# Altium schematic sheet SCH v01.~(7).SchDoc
size A3; SheetNumber: 1; SheetTotal: 1
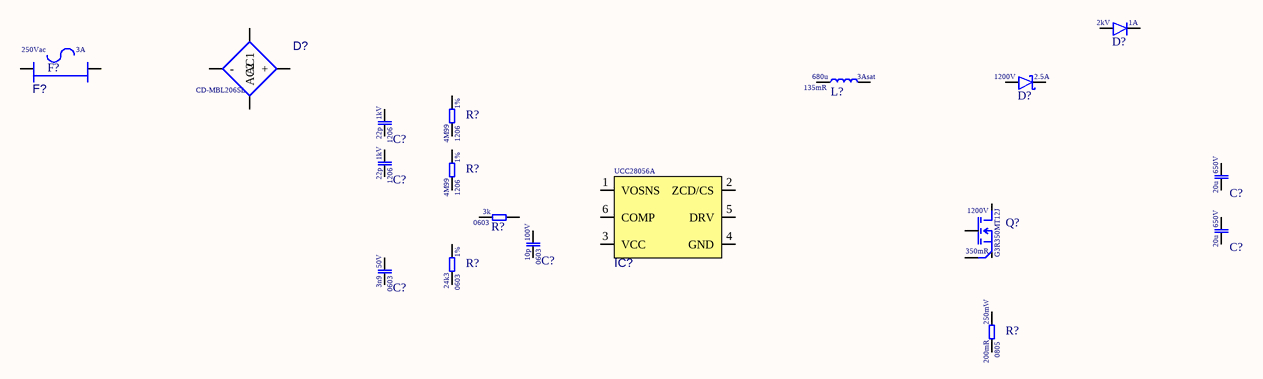
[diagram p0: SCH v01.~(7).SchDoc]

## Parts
(Parts that share a designator on the sheet are numbered #1, #2 ... from top to bottom, then left to right.)
C?#1  Voltage Rating: 1kV  Case Code (Imperial): 1206  Capacitance: 22p  [Cap_1206]  (hidden comment: Generic Capacitor model)
C?#2  Voltage Rating: 1kV  Case Code (Imperial): 1206  Capacitance: 22p  [Cap_1206]  (hidden comment: Generic Capacitor model)
C?#3  Voltage Rating: 650V  Capacitance: 20u  [C4AQCBW5200A3FJ]  (hidden comment: Generic Capacitor model)
C?#4  Voltage Rating: 650V  Capacitance: 20u  [C4AQCBW5200A3FJ]  (hidden comment: Generic Capacitor model)
C?#5  Voltage Rating: 100V  Case Code (Imperial): 0603  Capacitance: 10p  [CAP 0603]  (hidden comment: Generic Capacitor model)
C?#6  Voltage Rating: 50V  Case Code (Imperial): 0603  Capacitance: 3n9  [CAP 0603]  (hidden comment: Generic Capacitor model)
D?#1  Forward Current: 1A  Reverse Voltage: 2kV  [SOD-123FL]  (hidden comment: Diode)
D?#2  CD-MBL206SL  [CD-MBL206SL]
D?#3  Forward Current: 2.5A  Reverse Voltage: 1200V  [DO-214-2]  (hidden comment: Diode Schottky)
F?#1  Voltage: 250Vac  Hold Current: 3A  (hidden comment: Fuse no FP)  (graphical)
F?#2  64600001003  [64600001003]  (value not drawn)
IC?  UCC28056A  [SOT-23-6]
L?  Resistance: 135mR  Saturation current: 3Asat  Inductance: 680u  [60B684C]  (hidden comment: Inductor)
Q?  Manufacturer Part Number: G3R350MT12J  Rds: 350mR  Voltage: 1200V  [TO-263-7 D2PAK]  (hidden comment: Nmos_KS)
R?#1  Resistance Tolerance: 1%  Resistance: 4M99  Case Code (Imperial): 1206  [RES_1206]  (hidden comment: Generic resistor model)
R?#2  Resistance Tolerance: 1%  Resistance: 4M99  Case Code (Imperial): 1206  [RES_1206]  (hidden comment: Generic resistor model)
R?#3  Resistance: 3k  Case Code (Imperial): 0603  [RES_0603]  (hidden comment: Generic resistor model)
R?#4  Resistance Tolerance: 1%  Resistance: 24k3  Case Code (Imperial): 0603  [RES_0603]  (hidden comment: Generic resistor model)
R?#5  Resistance: 200mR  Power Rating: 250mW  Case Code (Imperial): 0805  [Res_0805]  (hidden comment: Generic resistor model)

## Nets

Not connected (* = marked no-connect by the designer): C?#1 1 2; C?#2 1 2; C?#3 1 2; C?#4 1 2; C?#5 1 2; C?#6 1 2; D?#1 A K; D?#2 + - AC1 AC2; D?#3 A K; F?#2 1 2; IC? 1(VOSNS) 2(ZCD/CS) 3(VCC) 4(GND) 5(DRV) 6(COMP); L? 1 2; Q? D G KS S; R?#1 1 2; R?#2 1 2; R?#3 1 2; R?#4 1 2; R?#5 1 2

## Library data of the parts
C?#1 C?#2 = Cap: Manufacturer: Walsin; Manufacturer Part Number: 1206N220J102CT
C?#3 C?#4 = Cap: Manufacturer: Kemet
C?#5 = Cap: Manufacturer: Kemet; Manufacturer Part Number: C0603C100J1GAC
C?#6 = Cap: Manufacturer: Vishay; Manufacturer Part Number: VJ0603Y392KXACW1BC
D?#1 = Diode: General Diode symbol; Manufacturer: MCC; Manufacturer Part Number: GS1Z-LTP
D?#2 = CD-MBL206SL: Diode Bridge 600V 2A; Manufacturer: Bourns
D?#3 = Diode Schottky: General Schottky Diode symbol; Manufacturer: GenerSiC; Manufacturer Part Number: GB01SLT12-214
F?#1 = Fuse no FP: Generic fuse symbol - no FP; Manufacturer: Littlefuse; Manufacturer Part Number: 06173.15MXP
F?#2 = 64600001003: Fuse Holder 5X20MM 250V 6.3A; Manufacturer: Littlefuse
IC? = UCC28056A: PFC TM IC; Manufacturer: Texas Instruments
L? = Inductor: Generic Inductor symbol; Manufacturer: Murata
Q? = Nmos_KS: Generic Nmos symbol with Kelvin Source; Manufacturer: GeneSiC
R?#1 R?#2 = Res: Manufacturer: ROHM; Manufacturer Part Number: KTR18EZPF4994
R?#3 = Res: Manufacturer: Yageo; Manufacturer Part Number: AC0603JR-073KL
R?#4 = Res: Manufacturer: Vishay; Manufacturer Part Number: CRCW060324K3FKEB
R?#5 = Res: Manufacturer: Eaton; Manufacturer Part Number: MFLA0805R2000FA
